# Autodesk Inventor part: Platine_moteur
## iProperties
Shininess: 64.0
Length Units: 11269
Angle Units: 11279
Time Units: 11290
Mass Units: 11283
Length Display Precision: 3
Angle Display Precision: 2
Compacted: True
Part Number: Platine_moteur
Document SubType Name: Modeling
Created: 2008-02
Material: Acier inoxydable - 440C
Designer: Pascal
Density: 0.0
Volumn: 0.0
Area: 0.0
PropertySet Name: Model Information
Control State: 0
Master: False
Checked Out: False
DESIGNATION: pièce
Author: Pascal
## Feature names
1. Extrusion1
2. Extrusion2
3. Réseau circulaire1 [Circular Pattern]
